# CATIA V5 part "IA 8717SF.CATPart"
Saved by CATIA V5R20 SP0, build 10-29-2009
Part number: IA 8717SF
Revision: ANY
Definition: UNKNOWN
Nomenclature: IA 8717SF
Source: Unknown
Bounding box of the stored display mesh (mm): x -4.35 to 4.35, y -17 to 0, z -4.35 to 4.35
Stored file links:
  C:\Users\Utente\Desktop\IO LAVORO\3D X SITO CF\CUMSA\3D files FA\FA 1687SF\IA 8717SF.CATPart

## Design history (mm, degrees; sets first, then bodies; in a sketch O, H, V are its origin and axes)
Body1 "Cortar-Extruir1" (main body)
  Solid1: solid without history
